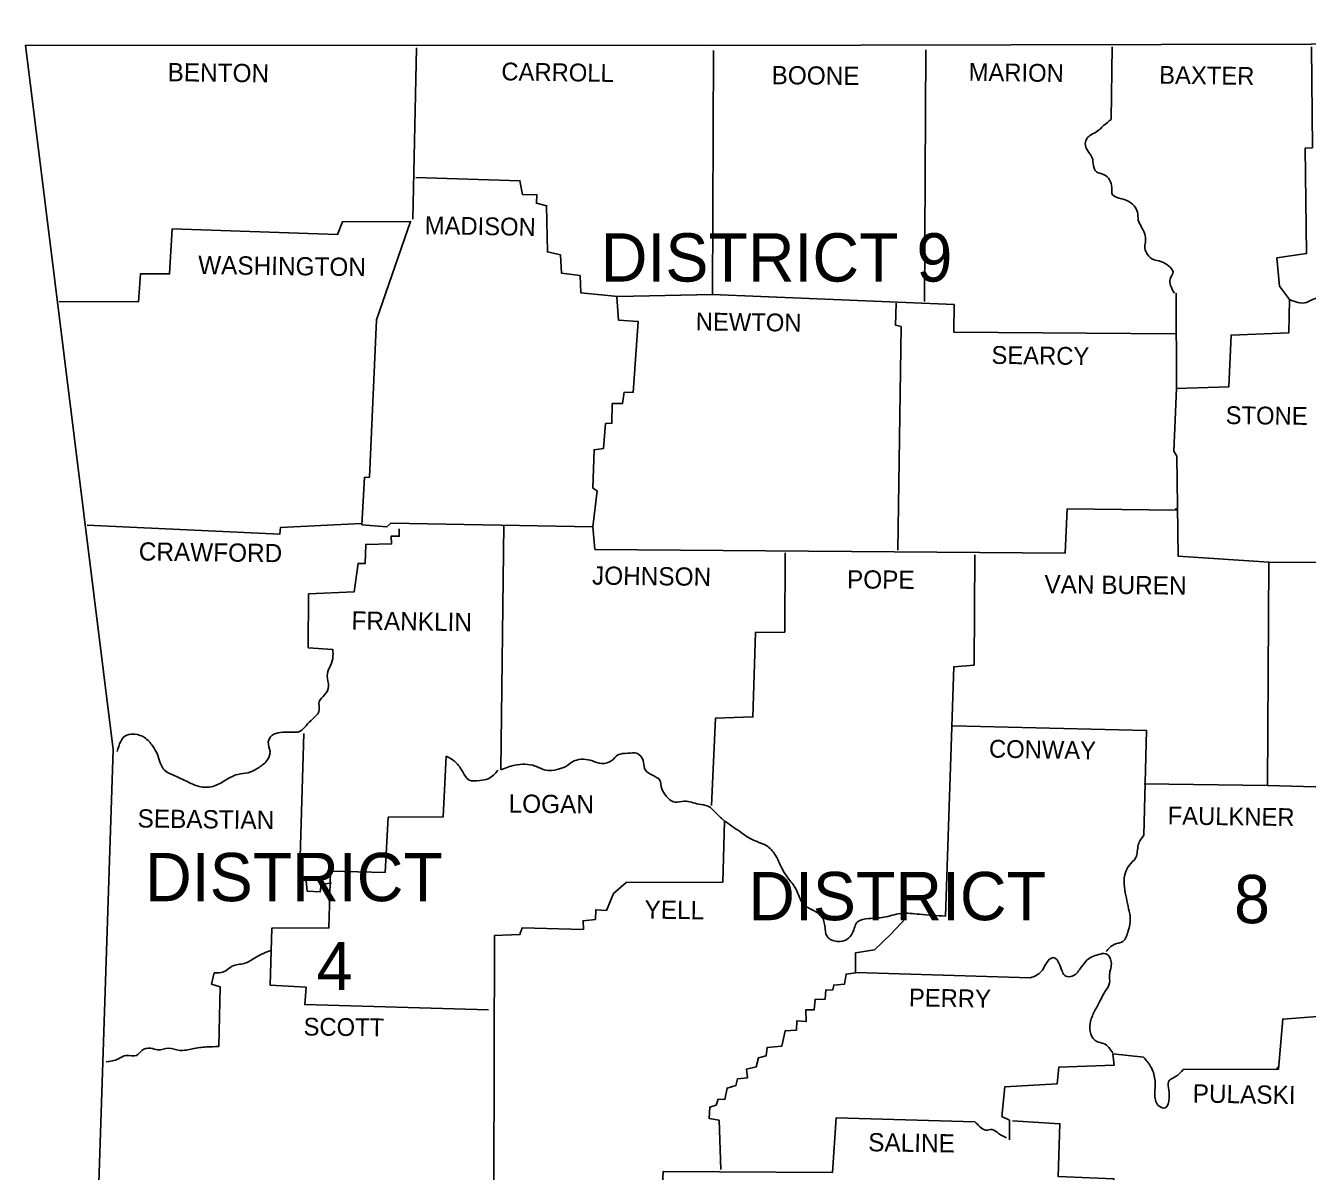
# Model space of a CAD drawing. Extents: x -33639 to 34530, y -17264 to 5867.
# Drawn here: x 1332 to 2998, y -8621 to -7133 of the extents above; entities that cross this region are included whole.
import ezdxf

# ---------------------------------------------------------------- set-up
doc = ezdxf.new("R2010")
doc.units = 0
for name, color, linetype in [('1', 7, 'Continuous'), ('2', 7, 'Continuous'), ('3', 7, 'Continuous')]:
    doc.layers.add(name, color=color, linetype=linetype)

msp = doc.modelspace()

# ---------------------------------------------------------------- linework, layer by layer
at = {"layer": '1'}
for points in [[(1332.2, -7158.5), (2222.1, -7159.1), (3003, -7157.4), (3924.3, -7143.1), (4351.4, -7133.2)], [(1332.2, -7158.5), (1446.1, -8073.2), (1396.6, -9566.3)], [(2743.8, -7160.7), (2742.7, -7254.9)], [(3003, -7160.7), (3004.1, -7291.7), (2994.8, -7292.3), (2996.4, -7429.3), (2957.9, -7434.8), (2961.2, -7471.7), (2974.4, -7488.8), (2973.3, -7532.2), (2898.5, -7535), (2895.7, -7602.1), (2827.5, -7604.3), (2824.2, -7685.8), (2828, -7692.4), (2829.7, -7822.3), (2947.5, -7830), (2945.8, -8120), (3039.4, -8122.8), (3039.4, -8417.8), (2965.6, -8423.3), (2960.1, -8488.2), (2836.3, -8488.8)], [(1840.1, -7161.9), (1835.2, -7384.7)], [(1839, -7330.3), (1974.4, -7334.7), (1977.7, -7352.3), (1996.4, -7352.8), (1995.9, -7363.8), (2009.1, -7367.1), (2010.2, -7427.1), (2027.3, -7431), (2028.4, -7454.6), (2052.6, -7457.9), (2053.7, -7480), (2101.6, -7484.9), (2224.8, -7482.2), (2225.9, -7165.7)], [(2501.7, -7164.6), (2500, -7491.5)], [(1375.6, -7491.5), (1478.6, -7492.1), (1481.3, -7455.7), (1519.3, -7455.7), (1522.6, -7396.9), (1737.2, -7404.6), (1743.8, -7388), (1832.4, -7387.5), (1787.9, -7515.2), (1779.1, -7719.4), (1772.4, -7719.9), (1769.1, -7781.5), (1801.6, -7784.3), (1806.6, -7779.3), (2069.1, -7784.3), (2071.8, -7813.5)], [(2100.5, -7486), (2102.7, -7515.7), (2128, -7517.4), (2121.4, -7609.8), (2109.8, -7609.3), (2107.6, -7624.1), (2094.4, -7624.1), (2093.9, -7649.5), (2085.6, -7650), (2082.8, -7682.5), (2070.7, -7684.1), (2069.1, -7733.7), (2074.6, -7737.5), (2069.1, -7784.3)], [(2224.8, -7482.2), (2538.5, -7495.4), (2538, -7531.1), (2825.8, -7533.3)], [(2463.1, -7493.7), (2462.6, -7522.3), (2469.7, -7524), (2465.3, -7814.6)], [(2827.5, -7604.3), (2826.9, -7480.5)], [(2071.8, -7813.5), (2682.7, -7818.4), (2685.5, -7760.6), (2827.5, -7762.3)], [(2825.8, -7761.7), (2827.5, -7760.1)], [(1412, -7782.1), (1662.4, -7793.7), (1663.5, -7784.9), (1768, -7779.9)], [(1817.6, -7786.5), (1817.6, -7796.4), (1807.1, -7796.4), (1807.7, -7806.3), (1774.1, -7806.9), (1773.5, -7831.6), (1764.2, -7831.6), (1759.2, -7868.5), (1699.8, -7871.3), (1699.3, -7941.2), (1731.2, -7943.4)], [(1953.5, -7782.1), (1949.7, -8099.7)], [(2318.9, -7817.9), (2318.4, -7920.8), (2280.4, -7921.3), (2277.1, -8030.9), (2228.7, -8032.5), (2223.2, -8145.9)], [(2565.5, -7820.6), (2564.4, -7963.7), (2538, -7965.9), (2527.5, -8289.5)], [(2947.5, -7830), (3230.3, -7831.6), (3254.6, -7820.1), (3252.9, -8035.3), (3236.4, -8042.4), (3221.5, -8055.1), (3216.6, -8060), (3216, -8121.7), (3036.1, -8121.7)], [(2536.9, -8042.4), (2788.4, -8048.5), (2785.1, -8184.4)], [(1693.7, -8052.3), (1688.2, -8241.6), (1696.5, -8243.8), (1698.1, -8257.1), (1714.7, -8258.2), (1716.3, -8248.8), (1729.5, -8246.6)], [(1878.7, -8082), (1874.8, -8160.7), (1803.3, -8161.3), (1799.4, -8232.8), (1728.4, -8231.2), (1726.2, -8304.9), (1651.9, -8305.5), (1649.7, -8379.2), (1696.5, -8382), (1694.8, -8404.5), (1933.7, -8411.2)], [(2785.6, -8117.8), (2945.8, -8120)], [(2240.2, -8166.2), (2238, -8245.5), (2112.6, -8246), (2096.1, -8260.4), (2086.7, -8282.4), (2072.9, -8281.3), (2072.4, -8293.9), (2056.4, -8295.6), (2057, -8307.1), (1977.2, -8304.9), (1974.4, -8313.7), (1941.4, -8314.8), (1940.3, -8636.8)], [(2476.3, -8291.7), (2456.5, -8313.2), (2435.1, -8333.6), (2410.3, -8337.4), (2410.3, -8363.3), (2398.2, -8364.9), (2396, -8378.1), (2382.2, -8379.2), (2381.1, -8385.3), (2371.8, -8385.8), (2371.2, -8397.4), (2358, -8397.9), (2356.9, -8411.2), (2345.9, -8411.2), (2346.5, -8426.6), (2334.4, -8425.5), (2333.8, -8437.6), (2318.9, -8438.7), (2314.5, -8458.5), (2295.8, -8460.1), (2294.2, -8471.1), (2284.3, -8473.9), (2281.5, -8485.5), (2268.9, -8488.2), (2270, -8499.8), (2257.3, -8500.9), (2255.1, -8509.7), (2243.6, -8513), (2240.8, -8527.8), (2232, -8527.3), (2229.2, -8535), (2221, -8537.7), (2220.4, -8552.6), (2233.1, -8554.8), (2235.3, -8618.6)], [(1583.1, -8459), (1584.8, -8381.4), (1573.8, -8378.1), (1577.1, -8363.3)], [(2637.6, -8369.9), (2410.9, -8362.7)], [(2784.5, -8472.8), (2744.9, -8468.4), (2746.6, -8483.2), (2674.5, -8486), (2672.3, -8507.5), (2604.6, -8511.3), (2600.7, -8549.8), (2610.6, -8554.8), (2610.6, -8580.1)], [(2957.4, -8487.7), (2960.1, -8484.9)], [(2565.5, -8557), (2385.5, -8551.5), (2380.6, -8622.5), (2160.4, -8621.4), (2159.3, -8645.1)], [(2614.5, -8555.3), (2676.1, -8559.2), (2673.9, -8628), (2746, -8630.7), (2747.1, -8690.7), (2781.2, -8693.5), (2781.2, -8703.9), (2813.2, -8706.1), (2814.3, -8744.7), (2886.9, -8744.7), (2889.1, -8782.6), (2956.3, -8785.9), (2955.7, -8857.5)]]:
    msp.add_lwpolyline(points, dxfattribs=at)
for points in [[(2742.7, -7254.9), (2732.8, -7263.1), (2724, -7270.8), (2710.8, -7280.2), (2709.1, -7289), (2713.6, -7297.8), (2718, -7304.9), (2719.6, -7314.8), (2723.5, -7323.1), (2732.8, -7326.4), (2740.5, -7333.6), (2743.3, -7343.5), (2744.4, -7352.8), (2753.2, -7357.2), (2763.1, -7360.5), (2772.4, -7367.1), (2776.8, -7375.4), (2777.9, -7385.8), (2781.8, -7394.1), (2786.2, -7404), (2787.3, -7412.3), (2786.2, -7420.5), (2788.4, -7428.2), (2795.6, -7435.9), (2808.2, -7439.8), (2817, -7445.3), (2823.1, -7453), (2819.2, -7462.3), (2819.8, -7470.6), (2824.7, -7480.5)], [(2974.4, -7488.8), (2996.4, -7492.6), (3009.6, -7487.7), (3019, -7502), (3024, -7513), (3032.2, -7528.9), (3045.4, -7533.9), (3055.3, -7542.7), (3055.3, -7552.1), (3046.5, -7560.9), (3039.9, -7569.7), (3042.1, -7580.1), (3044.3, -7594.4), (3044.3, -7608.2), (3041, -7620.8), (3038.3, -7632.4), (3041, -7642.3), (3051.5, -7640.7), (3062.5, -7632.4), (3074, -7632.4), (3085, -7638.5), (3096.6, -7648.9), (3108.2, -7646.7), (3117.5, -7644), (3130.7, -7640.1), (3140.1, -7645.1), (3148.3, -7651.7), (3158.2, -7662.1), (3167.6, -7668.7), (3179.7, -7674.8), (3194.6, -7678.6), (3208.3, -7688), (3210.5, -7703.9), (3210, -7717.7), (3208.9, -7734.8), (3207.8, -7753.5), (3209.4, -7771.6), (3215.5, -7783.8), (3223.2, -7798.1), (3225.4, -7811.3), (3224.8, -7832.2)], [(1731.2, -7943.4), (1731.2, -7954.9), (1726.8, -7967), (1724, -7977.5), (1725.7, -7991.2), (1720.7, -8002.2), (1713.6, -8011), (1713.6, -8022.1), (1705.3, -8033.6), (1696.5, -8042.4), (1688.8, -8049.6), (1675, -8050.7), (1663.5, -8051.2), (1651.9, -8055.1), (1647.5, -8063.3), (1649.7, -8076), (1645.3, -8088.1), (1633.8, -8097.5), (1621.1, -8103.5), (1607.9, -8105.7), (1589.7, -8114.5), (1573.2, -8121.7), (1555.6, -8120.6), (1539.1, -8113.4), (1524.2, -8106.8), (1512.7, -8100.2), (1503.3, -8079.8), (1497.3, -8068.8), (1486.8, -8057.8), (1474.2, -8053.4), (1463.7, -8054.5), (1451, -8076)], [(1949.7, -8099.7), (1967.8, -8093.6), (1981, -8092.5), (1994.2, -8094.7), (2008, -8100.2), (2022.9, -8099.1), (2033.9, -8095.3), (2044.9, -8088.1), (2057, -8085.9), (2068.5, -8088.1), (2080.6, -8091.4), (2093.9, -8087.5), (2101.6, -8080.4), (2114.8, -8078.2), (2126.3, -8078.2), (2134.6, -8087.5), (2136.2, -8097.5), (2146.7, -8106.8), (2156, -8112.9), (2158.8, -8124.4), (2163.7, -8132.7), (2168.7, -8138.2), (2175.9, -8141.5), (2188, -8140.4), (2206.7, -8144.2), (2218.8, -8147), (2229.8, -8156.3), (2240.2, -8166.2)], [(1878.7, -8082), (1890.8, -8089.7), (1900.1, -8102.4), (1908.4, -8112.9), (1922.1, -8113.4), (1933.2, -8111.2), (1945.8, -8100.2)], [(2240.2, -8166.2), (2259.5, -8179.5), (2277.7, -8191), (2296.4, -8199.3), (2306.8, -8211.4), (2316.2, -8230.1), (2323.9, -8241.6), (2333.8, -8256), (2341, -8271.9), (2352.5, -8280.7), (2364.6, -8288.4), (2370.7, -8302.2), (2373.4, -8315.9), (2386.6, -8322.5), (2399.3, -8319.8), (2406.5, -8311.5), (2413.1, -8297.2), (2427.9, -8292.8), (2447.2, -8291.2), (2469.2, -8286.2), (2493.4, -8287.3), (2527.5, -8289.5)], [(2785.1, -8184.4), (2777.9, -8197.1), (2774.6, -8213.6), (2765.8, -8224), (2760.3, -8236.1), (2759.8, -8252.1), (2762.5, -8266.4), (2765.3, -8280.2), (2767.5, -8292.8), (2764.7, -8308.8), (2757.6, -8322.5), (2746.6, -8326.4), (2736.1, -8335.8)], [(1577.1, -8363.3), (1589.2, -8362.2), (1600.7, -8354.5), (1616.1, -8351.2), (1631.6, -8342.9), (1650.8, -8334.1)], [(2637.6, -8369.9), (2651.4, -8362.2), (2658.5, -8350.6), (2667.3, -8343.5), (2676.1, -8353.4), (2683.8, -8367.7), (2692.1, -8367.7), (2702.5, -8357.8), (2709.1, -8349), (2717.4, -8342.4), (2726.2, -8339.6), (2735.6, -8338.5), (2742.7, -8349), (2740.5, -8365.5), (2740.5, -8376.5), (2734.5, -8388), (2727.9, -8400.1), (2720.7, -8413.9), (2715.2, -8428.8), (2716.3, -8443.1), (2724, -8452.4), (2732.8, -8455.2), (2744.9, -8467.3)], [(1583.1, -8459), (1567.2, -8459.6), (1549, -8461.8), (1532.5, -8464), (1517.6, -8461.2), (1503.9, -8463.4), (1494.5, -8461.2), (1483, -8464), (1476.4, -8470.6), (1462.6, -8470.6), (1452.7, -8475), (1436.7, -8478.8)], [(2784.5, -8472.8), (2793.9, -8484.9), (2799.4, -8501.4), (2799.4, -8520.1), (2803.8, -8535.5), (2812.6, -8538.8), (2818.1, -8525.6), (2817, -8512.4), (2817, -8504.7), (2826.4, -8498.1), (2836.3, -8488.8)], [(2606.8, -8577.4), (2596.3, -8571.9), (2588.1, -8566.9), (2579.3, -8567.5), (2572.1, -8563.1), (2565.5, -8557)]]:
    msp.add_spline(points, degree=3, dxfattribs=at)

# ---------------------------------------------------------------- texts
at = {"layer": '2'}
for s, height, rotation, p in [('BENTON', 23.67, 359.2527, (1516.5, -7205.3)), ('CARROLL', 23.11, 359.1481, (1950.2, -7204.2)), ('BOONE', 23.67, 359.4001, (2301.3, -7209.2)), ('MARION', 23.11, 359.1854, (2557.3, -7204.8)), ('BAXTER', 23.11, 359.2559, (2804.9, -7208.6)), ('MADISON', 23.11, 359.0906, (1850.6, -7404)), ('WASHINGTON', 23.66, 359.232, (1556.2, -7455.7)), ('NEWTON', 23.11, 359.2717, (2202.8, -7528.9)), ('SEARCY', 23.11, 359.2527, (2587, -7572.4)), ('STONE', 23.11, 359.4001, (2891.3, -7650.6)), ('CRAWFORD', 23.66, 359.2771, (1479.1, -7827.8)), ('JOHNSON', 23.67, 359.3514, (2068, -7859.1)), ('POPE', 23.67, 359.6155, (2399.3, -7864.1)), ('VAN BUREN', 23.67, 359.3508, (2655.8, -7870.2)), ('FRANKLIN', 23.67, 359.1815, (1755.4, -7917.5)), ('CONWAY', 23.11, 359.0371, (2583.7, -8083.7)), ('LOGAN', 23.67, 359.3969, (1959.6, -8155.2)), ('SEBASTIAN', 23.66, 359.2816, (1477.5, -8174.5)), ('FAULKNER', 23.11, 359.2486, (2815.9, -8170.6)), ('YELL', 23.67, 359.1987, (2136.2, -8292.8)), ('PERRY', 23.11, 359.0858, (2479.7, -8406.8)), ('SCOTT', 23.11, 359.4063, (1693.2, -8444.7)), ('PULASKI', 23.67, 359.053, (2848.4, -8531.7)), ('SALINE', 23.67, 359.1491, (2426.8, -8595))]:
    msp.add_text(s, height=height, rotation=rotation, dxfattribs=at).set_placement(p)
at = {"layer": '3'}
for s, height, p in [('DISTRICT 9', 62.74, (2079.5, -7465.6)), ('DISTRICT', 62.74, (1487.4, -8270.3)), ('DISTRICT', 62.74, (2271.1, -8295)), ('8', 62.7, (2902.3, -8298.9)), ('4', 62.7, (1710.3, -8385.8))]:
    msp.add_text(s, height=height, dxfattribs=at).set_placement(p)

doc.saveas('drawing.dxf')
